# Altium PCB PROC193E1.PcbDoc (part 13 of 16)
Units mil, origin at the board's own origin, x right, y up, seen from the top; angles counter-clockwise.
Board outline 7700 x 2300 mil, 6 copper layers (Top Layer, GND 1, SIG 1, PWR, GND 2, Bottom Layer), stack 60.98 mil thick; 946 components, 667 nets, 9401 pads, 1730 vias.
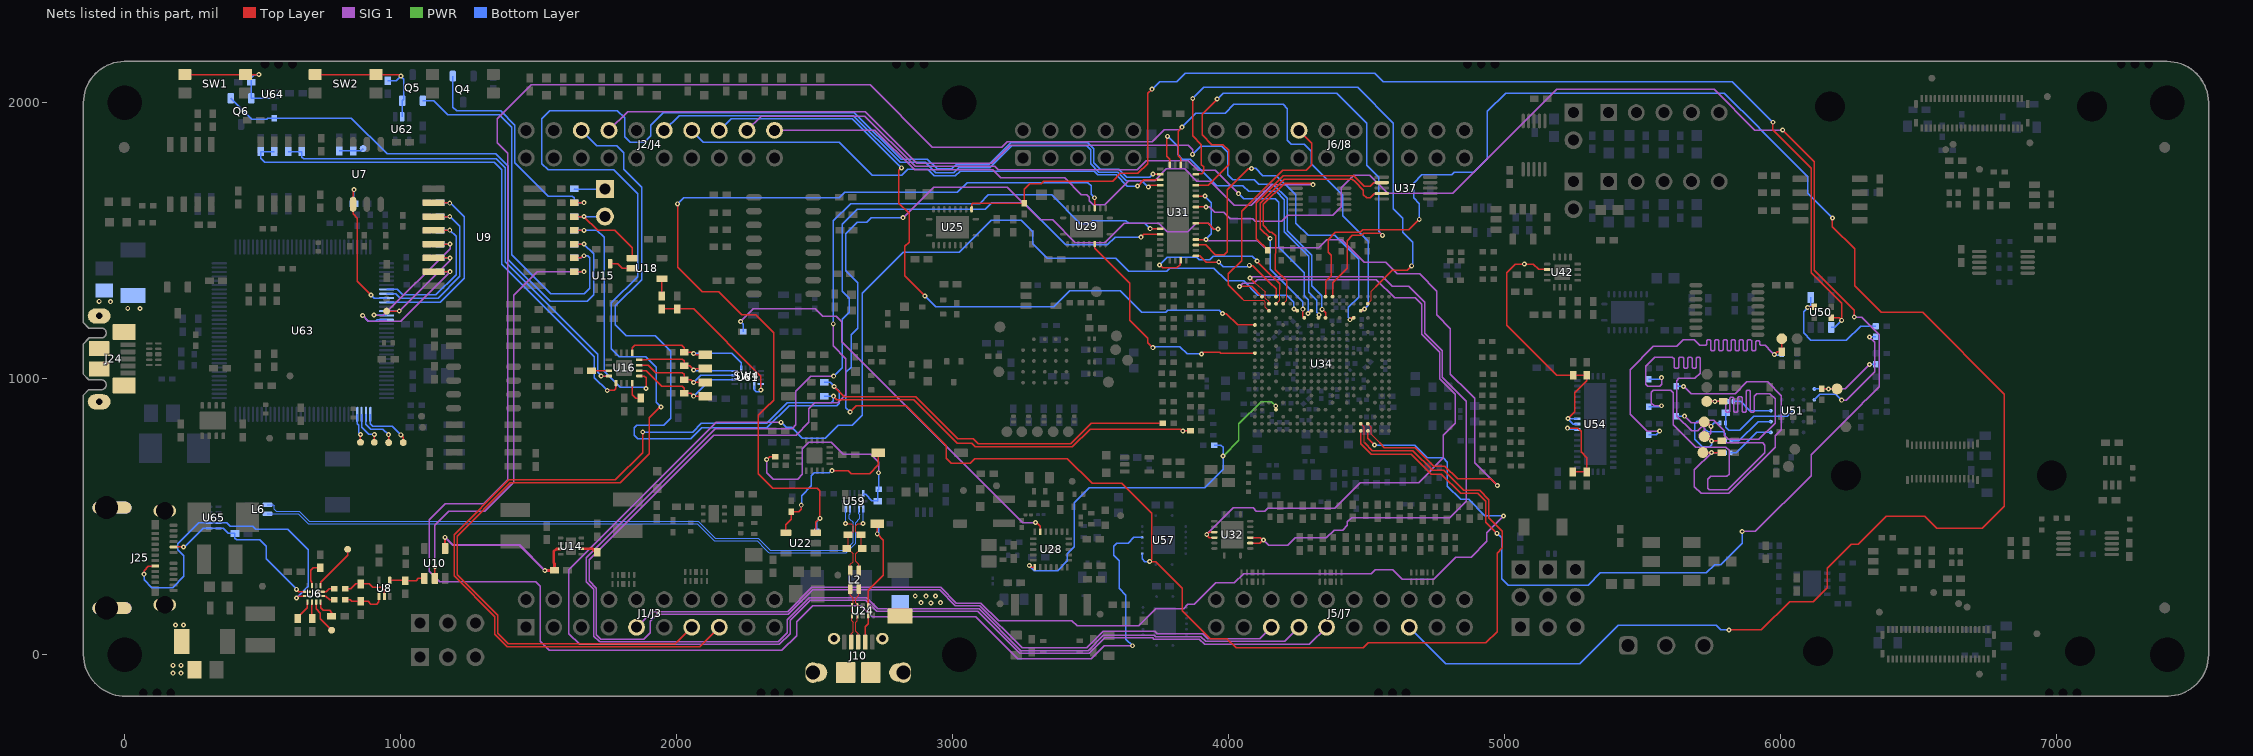
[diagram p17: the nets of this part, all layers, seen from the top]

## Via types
v1: diameter 18, hole 8, Top Layer to Bottom Layer, tented both sides, 1710 vias
v2: diameter 18, hole 8, Top Layer to Bottom Layer, tented top, 12 vias
v3: diameter 23.62, hole 11.81, Top Layer to Bottom Layer, tented both sides, 8 vias

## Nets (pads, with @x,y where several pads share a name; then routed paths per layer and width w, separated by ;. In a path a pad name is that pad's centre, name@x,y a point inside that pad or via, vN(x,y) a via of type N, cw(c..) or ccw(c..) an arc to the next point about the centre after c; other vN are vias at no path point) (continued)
OSPI1_D4_R: R204.2 R256.1 R292.2 TP39.1 | length 1490.1
  Top Layer w5.3: v1(5976.47,1087.55) 5986.85,1097.93 R204.2@6003.63,1097.93 TP39.1@6003.63,1145.32
  SIG 1 w4.75: v1(5561.09,810.56) 5515.88,810.56 5454.41,872.04 5454.41,1033.41 5538.71,1117.71 5622.8,1117.71 5647.22,1142.13 5686.03,1142.13 5707.16,1121 5725.58,1121 5727.95,1121 5731.64,1124.69 5731.64,1137.31 5735.33,1141 5742.7,1141 5746.39,1137.31 5746.39,1104.69 5750.08,1101 5757.45,1101 5761.14,1104.69 5761.14,1137.31 5764.83,1141 5772.2,1141 5775.89,1137.31 5775.89,1104.69 5779.58,1101 5786.95,1101 5790.64,1104.69 5790.64,1137.31 5794.33,1141 5801.7,1141 5805.39,1137.31 5805.39,1104.69 5809.08,1101 5816.45,1101 5820.14,1104.69 5820.14,1137.31 5823.83,1141 5831.2,1141 5834.89,1137.31 5834.89,1104.69 5838.58,1101 5845.95,1101 5849.64,1104.69 5849.64,1137.31 5853.33,1141 5860.7,1141 5864.39,1137.31 5864.39,1104.69 5868.08,1101 5875.45,1101 5879.14,1104.69 5879.14,1137.31 5882.83,1141 5890.2,1141 5893.89,1137.31 5893.89,1104.69 5897.58,1101 5904.95,1101 5908.64,1104.69 5908.64,1134.74 5912.33,1138.43 5919.7,1138.43 5923.39,1134.74 5923.39,1124.69 5927.08,1121 5943.03,1121 5965.24,1098.79 v1(5976.47,1087.55)
  Bottom Layer w5.3: R292.2@5521.14,798.02 5548.55,798.02 v1(5561.09,810.56) ; v1(5976.47,1087.55) 5978.51,1085.52 6002.46,1085.52 R256.1@6003.63,1084.35
OSPI1_D5: R268.2 U51.E3 | length 150.5
  Bottom Layer w5.3: R268.2@5827.65,917.95 5854.05,917.95 5887.66,884.34 U51.E3@5964.26,884.34
OSPI1_D5_R: R198.2 R268.1 R284.2 TP36.1 | length 1307.3
  Top Layer w5.3: TP36.1@5731.56,917.99 v1(5760.91,917.95) v1(5760.91,917.95) R198.2@5791.82,917.95
  SIG 1 w4.75: v1(5651.46,864.43) 5674.73,841.16 5699.25,841.16 5708.09,850 5756.74,850 5795.77,810.98 5795.77,795.37 5810.13,781 5920.33,781 5979,839.67 5979,926.86 5959.86,946 5913.09,946 5903.81,936.72 5903.81,881.64 5900.12,877.95 5892.75,877.95 5889.06,881.64 5889.06,954.26 5885.37,957.95 5878,957.95 5874.31,954.26 5874.31,881.64 5870.62,877.95 5863.25,877.95 5859.56,881.64 5859.56,931.49 5855.87,935.18 5848.5,935.18 5844.81,931.49 5844.81,881.64 5841.12,877.95 5833.75,877.95 5830.06,881.64 5830.06,928.95 5826.37,932.64 5819,932.64 5815.31,928.95 5815.31,881.64 5811.62,877.95 5804.25,877.95 5800.56,881.64 5800.56,914.26 5796.87,917.95 v1(5760.91,917.95)
  Bottom Layer w5.3: R284.2@5621.27,864.54 5651.35,864.54 v1(5651.46,864.43) ; v1(5760.91,917.95) R268.1@5807.57,917.95
OSPI1_D6: R272.2 U51.E2 | length 174
  Bottom Layer w5.3: R272.2@5819.22,775.07 5848.55,775.07 5918.45,844.97 U51.E2@5964.26,844.97
OSPI1_D6_R: R194.2 R272.1 R295.2 TP35.1 | length 1658.1
  Top Layer w5.3: TP35.1@5723.41,790.88 5733.29,790.88 v1(5749.1,775.07) R194.2@5785.55,775.07
  SIG 1 w4.75: v1(5568.23,902.32) 5540.61,902.32 5530.7,912.23 5530.7,952.06 5537.54,958.9 5601.25,958.9 5610.02,950.13 5610.02,832.88 5691.33,751.58 5801.03,751.58 5812.38,740.23 5812.38,654.61 5804.78,647 5745.52,647 5735.03,636.51 5735.03,604.02 5740.64,598.41 5808.32,598.41 5942.31,732.4 5942.31,759.45 5934.1,767.65 5788.42,767.65 5781,775.07 v1(5749.1,775.07)
  Bottom Layer w5.3: R295.2@5520.97,898.04 5521.18,898.25 5565.96,898.25 5568.23,900.52 v1(5568.23,902.32) ; v1(5749.1,775.07) 5749.1,760.2 5742.7,753.79 5714.8,753.79 5688.28,780.31 5688.28,836.39 5697.82,845.93 5715.61,845.93 5723.29,838.24 5723.29,819.7 5735.52,807.47 5792.53,807.47 5799,801 5799,777.69 5796.38,775.07 R272.1@5799.14,775.07
OSPI1_D7: R271.2 U51.E1 | length 175.6
  Bottom Layer w5.3: R271.2@5819.22,731.78 5839.07,731.78 5912.89,805.6 U51.E1@5964.26,805.6
OSPI1_D7_R: R193.2 R271.1 R285.2 TP33.1 | length 1266.5
  Top Layer w5.3: TP33.1@5717.64,732.72 v1(5749.1,732.7) 5750.02,731.78 R193.2@5785.55,731.78
  SIG 1 w4.75: v1(5647.75,972.46) 5674.85,945.37 5834.14,945.37 5877.35,988.58 5952.66,988.58 6002.19,939.05 6002.19,816.27 5979.46,793.54 5979.46,752.61 5811.85,585 5711,585 5687,609 5687,670.6 v1(5749.1,732.7)
  Bottom Layer w5.3: R285.2@5621.27,972.25 5647.54,972.25 v1(5647.75,972.46) ; v1(5749.1,732.7) 5749.56,732.24 5798.68,732.24 R271.1@5799.14,731.78
OSPI1_DQS: R195.2 R199.1 R273.2 U51.C3 | length 330.3
  Bottom Layer w5.3: R195.2@5800.04,877.17 5800,877.12 R273.2@5800,840 5800,824 5811,813 5851,813 5902.48,864.48 6023.13,864.48 U51.C3@6043,884.34
OSPI1_DQS_R: R273.1 R293.2 TP34.1 | length 1228.2
  Top Layer w5.3: TP34.1@5722.55,844.01 5730.67,844.01 v1(5746.91,827.76)
  SIG 1 w4.75: v1(5568.23,1003.98) 5568.23,979.41 5561.82,973 5518.01,973 5510.69,980.32 5510.69,1045.86 5543.43,1078.6 5607.4,1078.6 5613.3,1072.7 5613.3,1042.65 5617.85,1038.1 5625.75,1038.1 5630.19,1042.54 5630.19,1074.79 5634,1078.6 5645.09,1078.6 5648.77,1074.91 5648.77,1042.28 5652.46,1038.6 5659.84,1038.6 5663.52,1042.28 5663.52,1074.91 5667.21,1078.6 5674.59,1078.6 5678.27,1074.91 5678.27,1042.28 5681.96,1038.6 5689.34,1038.6 5693.02,1042.28 5693.02,1074.91 5696.71,1078.6 5704.09,1078.6 5707.77,1074.91 5707.77,1019.81 5689.09,1001.13 5630.54,1001.13 5623.09,993.68 5623.09,864.76 5676.82,811.04 5698.45,811.04 5713.31,825.9 5718.53,825.9 5723.74,820.68 5723.74,815.47 5704.67,796.4 5704.67,787.46 5712.17,779.96 5724.25,779.96 5735.17,790.88 5746.72,802.42 5746.72,827.56 v1(5746.91,827.76)
  Bottom Layer w4.75: v1(5746.91,827.76) 5759.16,840 R273.1@5779.92,840
  Bottom Layer w5.3: R293.2@5521.14,999.2 5560.02,999.2 5564.79,1003.98 v1(5568.23,1003.98)
OSPI1_ECC_FAIL: R207.1 R249.2 TP43.1 U51.A5 | length 314.6
  Top Layer w5.3: R207.1@6148.3,963.43 v1(6172.35,963.43) TP43.1@6203.88,963.43
  SIG 1 w4.75: v1(6172.35,963.43) 6233.36,963.43 v1(6321.24,1051.32)
  Bottom Layer w5.3: U51.A5@6121.74,963.08 6172,963.08 v1(6172.35,963.43) ; v1(6321.24,1051.32) 6322.31,1052.39 R249.2@6343.71,1052.39
OSPI1_MUX_EN: R186.2 R189.1 U54.8 | length 297.3
  Top Layer w5.3: v1(5227.45,820.93) 5264.55,820.93 5276.18,809.3 5276.18,734.85 5297.29,713.74 R189.1@5297.29,662.45 R186.2@5246.75,662.45
  Bottom Layer w5.3: v1(5227.45,820.93) 5232.03,816.35 U54.8@5263.12,816.35
OSPI1_MUX_SEL: R187.2 R190.1 U42.10 U54.9 U54.10 | length 987
  Top Layer w5.3: U42.10@5153.4,1396.06 5123.08,1396.06 5103.39,1415.74 v1(5070.7,1415.74) 5038.35,1415.74 5007.2,1384.59 5007.2,1194.57 5088.74,1113.03 5188.8,1012.97 R187.2@5247.81,1012.97 ; v1(5228.77,855.72) 5254.15,881.1 5254.15,949.53 5297.67,993.06 R190.1@5297.67,1012.97 R187.2@5247.81,1012.97 ; R187.2@5248.75,1012.03 R187.2@5247.81,1012.97
  Bottom Layer w5.3: U54.9@5263.12,836.03 5248.45,836.03 v1(5228.77,855.72) U54.10@5263.12,855.72
OSPI1_RESET_OUT0: R93.2 R208.1 U25.12 U50.1 | length 4280.2
  Top Layer w5.3: U25.12@3067.87,1614.03 3067.87,1631.81 3072.56,1636.5 R93.2@3258.14,1636.5 3258.14,1686.14 3278.82,1706.82 3320.61,1706.82 3329.98,1716.2 3578.69,1716.2 3607.11,1744.61 3670.42,1744.61 3705.83,1780.03 3705.83,2034.45 v1(3722.17,2049.21) ; v1(5971.5,1929.49) 5971.5,1902.37 6110.42,1763.45 6110.42,1383.57 6220.63,1273.37 v1(6220.63,1211.87) 6211.55,1220.95 R208.1@6182.93,1220.95
  Bottom Layer w5.3: v1(3722.17,2049.21) 3722.39,2049.21 3749.54,2076.36 3812.03,2076.36 3843.02,2107.35 4529.36,2107.35 4560.35,2076.36 5824.63,2076.36 v1(5971.5,1929.49) ; U50.1@6182.93,1186.5 6195.25,1186.5 v1(6220.63,1211.87)
OSPI1_RSTn: R247.2 U51.A4 | length 435.8
  SIG 1 w4.75: v1(6220.63,922.47) 6237.35,922.47 6340.77,1025.89 6340.77,1131.82 v1(6321.24,1151.35)
  Bottom Layer w5.3: U51.A4@6121.74,923.71 6141.55,943.52 6199.57,943.52 v1(6220.63,922.47) ; v1(6321.24,1151.35) 6321.7,1151.81 R247.2@6344.52,1151.81
OSPI1_RSTn_R: R206.1 R241.1 R247.1 U50.4 | length 459.3
  Top Layer w5.3: v1(6097.5,1257.86) 6100.94,1257.86 6103.4,1260.32 R206.1@6121.79,1260.32
  Bottom Layer w5.3: U50.4@6108.12,1294.77 6108.12,1266.82 6099.16,1257.86 v1(6097.5,1257.86) 6082.58,1242.93 6082.58,1166.39 6108.97,1139.99 6237.78,1139.99 6288.97,1191.18 R247.1@6344.52,1191.18
PMIC_INTn_GPIO0: R322.1 U28.13 U34.U4 | length 1435.5
  Top Layer w5.3: v1(3277.12,323.02) 3278.06,323.02 3284.01,317.07 U28.13@3296.9,317.07 ; v1(4170.16,901.47) 4170.16,889.25 U34.U4@4171.26,888.16
  PWR w4.75: v1(3979.2,719.87) 4036.41,777.09 4036.41,836.41 4117,917 4154.63,917 v1(4170.16,901.47)
  Bottom Layer w5.3: v1(3277.12,323.02) 3295.38,304.77 3379.73,304.77 3414.94,339.98 3414.94,366.24 3439.69,390.99 3439.69,550.57 3494.32,605.2 3912.65,605.2 3979.2,671.75 v1(3979.2,719.87) 3979.2,751.51 3971.18,759.53 R322.1@3947.06,759.53
PMIC_NRST: R365.1 U28.6 | length 1533.2
  Top Layer w5.3: v1(3300,478.86) 3302.43,476.43 3306.01,476.43 3316.58,465.85 U28.6@3316.58,446.5
  SIG 1 w4.75: v1(2231.35,1207.91) 2277.09,1253.66 2501.76,1253.66 2528.33,1227.09 2576.86,1227.09 2597.54,1206.4 2597.54,1134.49 3253.17,478.86 v1(3300,478.86)
  Bottom Layer w5.3: v1(2231.35,1207.91) 2240.87,1198.39 R365.1@2240.87,1170.68
PORZ_DELAY: U15.4 U18.2 | length 86.3
  Top Layer w5.3: U15.4@1758.55,1416.81 1785.92,1416.81 1802.85,1399.88 U18.2@1837.83,1399.88
PORZ_PB: Q6.2 R410.1 SW1.2 SW1.4 U64.1 | length 436
  Top Layer w5.3: SW1.2@217.32,2102.28 SW1.4@437.8,2102.28 v1(485.53,2102.28)
  Bottom Layer w5.3: Q6.2@458.54,2016.24 458.02,2016.77 R410.1@458.02,2074.5 458.02,2090.5 469.81,2102.28 v1(485.53,2102.28) ; Q6.2@458.71,2016.42 U64.1@519.68,2016.42
PR1_PRU0_GPIO0: J2/J4.11 U34.B5 | length 2828.6
  Top Layer w3.94: U34.B5@4196.85,1272.01 4209.64,1284.81 4209.64,1325.16
  Top Layer w5.3: 4209.64,1325.16 4209.64,1354.54 4168.79,1395.4 4168.79,1399.79 4169.58,1508.29 4169.58,1518.19 4156.04,1531.73 4148.61,1531.73 4124.7,1555.63 4124.7,1631.9 4202.17,1709.37 4295.19,1709.37 4301.14,1703.43 v1(4304.58,1703.43)
  SIG 1 w4.75: J2/J4.11@2354.17,1900 2718,1900 2861.45,1756.55 3144.45,1756.55 3173.4,1727.6 3405.08,1727.6 3465.78,1666.9 3466.43,1666.9 3466.53,1666.8 3481.75,1666.8 3481.85,1666.9 3486.18,1666.9 3494.62,1658.46 3494.62,1645.33 3509.55,1630.4 3550.13,1630.4 3637.55,1717.82 3730.82,1717.82 3773.38,1760.38 3839.62,1760.38 3884.11,1715.89 3932.07,1715.89 4019.17,1628.8 4081.34,1628.8 4155.96,1703.43 v1(4304.58,1703.43)
PR1_PRU0_GPIO1: U31.22 U34.A4 | length 371.7
  Top Layer w5.3: U31.22@3881.04,1445.5 3895.43,1445.5 3917.88,1423.04 v1(3963.61,1423.04) ; v1(4074.24,1411.06) 4074.92,1410.38 4086.93,1410.38 4148.88,1348.43 4171.26,1326.05 4171.26,1313.55 U34.A4@4171.26,1297.6
  Bottom Layer w5.3: v1(3963.61,1423.04) 3979.88,1406.77 4066.52,1406.77 4070.8,1411.06 v1(4074.24,1411.06)
PR1_PRU0_GPIO2: U31.20 U34.B4 | length 677
  Top Layer w3.94: U34.B4@4171.26,1272.01 4184.05,1284.81 4184.05,1325.16
  Top Layer w5.3: v1(3749.2,1412.38) 3749.53,1412.38 3760.42,1401.5 3812.21,1401.5 3823.65,1412.94 3823.65,1427.48 U31.20@3825.92,1429.75 ; v1(4103,1427) 4103,1424.85 4128.3,1399.55 4184.05,1343.8 4184.05,1325.16
  Bottom Layer w5.3: v1(3749.2,1412.38) 3777.66,1440.84 3883.95,1440.84 3892.68,1432.11 3931.63,1432.11 3944.13,1444.61 4085.39,1444.61 v1(4103,1427)
PR1_PRU0_GPIO5: U32.11 U32.12 U34.B3 | length 2500
  Top Layer w3.94: 4094.91,1348.43 4131.52,1315.1 4132.81,1313.82 4132.81,1302.97 4132.87,1302.9 4132.87,1291.45 4143.88,1280.45 4143.88,1273.8 U34.B3@4145.67,1272.01
  Top Layer w5.3: v1(4076.31,1365.36) 4094.91,1348.43 ; U32.11@4077.76,404.97 4112.62,404.97 v1@4122.8,415.14 ; U32.12@4077.76,424.65 4113.2,424.65 4122.71,415.14 v1@4122.8,415.14 ; v1@4126.14,415.14 v1@4122.8,415.14 ; v1(4126.14,415.42) 4123.07,415.42 v1@4122.8,415.14
  SIG 1 w4.75: v1(4076.31,1365.36) 4079.9,1365.36 4083.89,1369.35 4557.02,1369.35 4591.5,1334.87 4652.08,1334.87 4710.4,1276.54 4710.4,1164.29 4773.67,1101.01 4773.67,1005.15 4860.2,918.62 4860.2,556.87 4800.4,497.08 4445.28,497.08 4429.79,481.58 4429.79,468.61 4412.56,451.39 4381.38,451.39 4353.9,423.91 4240.34,423.91 4213.49,397.06 4144.5,397.06 v1(4126.14,415.42)
PR1_PRU0_GPIO6: U32.4 U32.5 U34.A2 | length 2474.4
  Top Layer w5.3: U32.5@3947.84,424.65 3929.76,424.65 3920.05,434.36 v1(3920.05,436.01) 3920.7,436.01 3929.03,444.34 U32.4@3947.84,444.34 ; v1(4039.25,1334.87) 4082.81,1334.87 U34.A2@4120.08,1297.6
  SIG 1 w4.75: v1(4039.25,1334.87) 4050.22,1345.83 4089.15,1345.83 4102.92,1359.6 4534.99,1359.6 4601.25,1293.34 4676.41,1293.34 4698.88,1270.87 4698.88,1160.82 4763.92,1095.77 4763.92,1000.05 4820,943.97 4820,839.2 4777.12,796.33 4777.12,713.12 4687.35,623.35 4649.81,623.35 4649.81,623.15
  SIG 1 w5.3: v1(3920.05,436.01) 4016.05,532 4088.46,532 4099.55,520.91 4131.1,520.91 4141.97,531.78 4384.1,531.78 4475.47,623.15 4649.81,623.15
PR1_PRU0_GPIO7: U34.D8 U37.4 | length 1002.7
  Top Layer w5.3: v1(4150.06,1508.43) 4114.1,1544.39 4114.1,1636.29 4201.54,1723.73 4447.3,1723.73 4457.41,1713.62 4487.89,1683.15 4487.89,1666.56 4499.26,1655.19 4512.89,1655.19 4527.86,1670.15 4553.02,1670.15 U37.4@4554.27,1671.4 ; v1(4268.07,1252.23) 4268.07,1226.38 U34.D8@4273.62,1220.83
  Bottom Layer w5.3: v1(4150.06,1508.43) 4150.06,1397.46 4199.09,1348.43 4268.07,1279.45 v1(4268.07,1252.23)
PR1_PRU0_GPIO8: J6/J8.57 U34.C3 | length 951
  Top Layer w3.94: 4048.24,1290.58 4054.02,1284.81 4125.98,1284.81 4132.96,1277.83 4132.96,1277.4 4132.87,1277.31 4132.87,1259.22 U34.C3@4145.67,1246.42
  Top Layer w5.3: 4048.24,1290.58 3998.46,1340.37 3998.46,1380.46 4046.6,1428.6 4046.6,1536.54 4046.43,1536.71 4046.43,1552.89 4046.6,1553.06 4046.6,1607.32 4194.73,1755.45 4280.06,1755.45 4300.22,1775.61 4300.22,1853.95 J6/J8.57@4254.17,1900
PR1_PRU0_GPIO9: R133.1 U37.2 | length 705
  Top Layer w5.3: R133.1@4140.45,1465.23 4140.45,1467.2 4099.9,1507.75 4099.9,1626.92 4099.9,1637.08 4198.1,1735.28 4452.85,1735.28 4490.84,1697.29 4512.66,1697.29 4525.37,1710 4553.51,1710 U37.2@4554.27,1710.77
PR1_PRU1_GPIO0: U31.28 U34.W16 U57.10 | length 6452.4
  Top Layer w3.94: U34.W16@4478.34,836.97 4491.14,824.18 4491.14,768.57 4491.87,767.84
  Top Layer w5.3: v1(2628.07,880.01) 2650.1,902.04 2832.07,902.04 2976.16,757.95 2976.16,711.67 2993.97,693.86 3062.73,693.86 3080,711.13 3415.21,711.13 3504.49,621.85 3611.35,621.85 3611.64,621.57 3612.06,621.57 3721.06,512.57 3721.06,345.63 v1(3713.33,337.9) 3735.19,337.9 3831.36,241.73 3831.36,160.43 3932.82,58.96 3992.14,58.96 4026.38,24.72 4035.88,24.72 4222.29,24.72 4482.79,24.72 4486.91,24.72 4505.65,43.46 4931.16,43.46 4972,84.3 4972,368.25 4990.81,387.07 4990.81,448.36 4942.13,497.03 4942.13,561.96 4908.44,595.65 4907.04,595.65 4906.89,595.8 4850.79,595.8 4778.71,667.88 4738.8,667.88 4666.72,739.95 4519.76,739.95 4491.87,767.84 ; U31.28@3881.04,1563.61 3900.05,1563.61 3900.18,1563.73 3908.57,1563.73 3908.78,1563.95 3908.97,1563.77 3925.15,1563.77 3946.32,1542.59 v1(3960.53,1542.59)
  SIG 1 w4.75: v1(2819.73,1583.71) 2930.38,1694.36 3197.62,1694.36 3316.38,1575.6 3362.12,1575.6 3444.3,1493.42 3546.46,1493.42 3546.76,1493.72 3550.94,1493.72 3621.17,1563.95 3746.99,1563.95 3777.6,1533.34 3778.11,1532.83 3851.31,1532.83 3882.25,1563.77 3924.96,1563.77 3946.13,1542.59 v1(3960.53,1542.59)
  Bottom Layer w5.3: v1(2628.07,880.01) 2612.28,895.8 2612.28,1023.29 2631.5,1042.52 2631.5,1159.02 2655.9,1183.41 2655.9,1347.2 2611.47,1391.62 2611.47,1526.06 2653.13,1567.72 2688.57,1567.72 2704.57,1583.71 v1(2819.73,1583.71) ; U57.10@3686.31,366.41 3686.31,347.3 3696,337.61 v1@3713.04,337.61
PR1_PRU1_GPIO1: U31.31 U34.Y16 | length 6227.5
  Top Layer w5.3: U31.31@3881.04,1622.66 v1(3917.06,1622.66) ; U34.Y16@4478.34,811.38 4478.34,765.07 4516.84,726.57 4660.54,726.57 4732.88,654.24 4770.64,654.24 4839.67,585.2 4902.5,585.2 4931.53,556.17 4931.53,484.46 ; 4931.51,484.43 4931.51,480.04 v1(4971.28,440.27) ; v1(6006.75,1901.33) 6121.02,1787.06 6121.02,1393.9 6266.12,1248.81 v1(6266.12,1223.61)
  SIG 1 w4.75: v1(3917.06,1622.66) 3929.39,1622.66 3949.48,1602.57 3982.5,1602.57 4004.65,1580.42 4086.16,1580.42 4096.57,1570.01 4191.76,1570.01 4213.72,1591.97 4376.94,1591.97 4407.52,1622.55 4407.52,1691.39 4453,1736.87 4510.73,1736.87 4575.85,1671.75 4811.01,1671.75 5187.84,2048.57 5758.43,2048.57 5905.67,1901.33 v1(6006.75,1901.33) ; v1(5860.13,447.11) 5908.28,447.11 6110.17,649 6110.17,724.35 6295.62,909.81 6295.62,910.61 6306.39,921.38 6307.19,921.38 6356.33,970.52 6356.33,1160.5 6293.22,1223.61 v1(6266.12,1223.61)
  Bottom Layer w5.3: v1(4971.28,440.27) 4988.11,423.45 4988.11,276.36 5012.39,252.08 5038.58,252.08 5038.76,252.26 5074.39,252.26 5074.57,252.08 5138.58,252.08 5138.76,252.26 5174.39,252.26 5174.57,252.08 5238.58,252.08 5238.76,252.26 5274.39,252.26 5274.57,252.08 5301.85,252.08 5346.36,296.58 5730.4,296.58 5760.2,326.38 5781.76,326.38 5860.13,404.75 v1(5860.13,447.11)
PR1_PRU1_GPIO2: U31.25 U31.33 U34.W17 | length 2555.4
  Top Layer w3.94: U34.W17@4503.93,836.97 4516.73,824.18 4516.73,816.68 4516.73,806.08 ; 4516.72,806.07 4516.72,798.65 4519.87,795.5 4547.51,767.84 4546.59,767.84
  Top Layer w5.3: U31.25@3881.04,1504.55 3881.18,1504.69 3916.92,1504.69 v1(3917.06,1504.83) ; U31.33@3881.04,1662.03 v1(3913.33,1662.03) ; 4546.59,767.84 4563.58,750.85 4564.52,750.85 4564.82,750.55 4674.79,750.55 4742.32,683.03 4782.84,683.03 4828.83,637.04 4949.14,637.04 v1(4972.77,613.42)
  SIG 1 w4.75: v1(3917.06,1504.83) 3921.4,1500.48 4104.98,1500.48 4130.49,1474.98 4325.26,1474.98 4354.39,1504.11 4409.86,1504.11 4491.64,1422.33 4567.79,1422.33 4610.35,1379.76 4691.21,1379.76 4753.92,1317.05 4753.92,1230.35 4754.61,1229.66 4754.61,1229.5 4802.92,1181.2 4802.92,1126.67 4802.77,1126.52 4802.77,1106.64 4802.92,1106.48 4802.92,1021 4802.92,1017.29 4869.22,950.99 4891,929.21 4891,695.18 v1(4972.77,613.42)
  Bottom Layer w5.3: v1(3913.33,1662.03) 3937.3,1638.06 3937.3,1525.06 v1(3917.06,1504.83)
PR1_PRU1_GPIO3: U31.35 U34.A12 | length 1865.5
  Top Layer w5.3: U31.35@3881.04,1701.4 3925.12,1701.4 3999.65,1775.94 3999.65,1827.51 3978.52,1848.65 3938.84,1848.65 3903.64,1883.85 3903.64,1959.35 v1(3957.85,2013.56) ; U34.A12@4375.98,1297.6 4375.98,1347.07 4377.34,1348.43 4428.76,1399.85 4428.76,1500.95 4447.36,1519.54 4482.04,1519.54 4489.67,1527.17 4549.29,1527.17 v1(4556.67,1519.78)
  Bottom Layer w5.3: v1(3957.85,2013.56) 3979.54,2035.25 4390.41,2035.25 4499.89,1925.77 4499.89,1781.68 4499.89,1773.37 4542.59,1730.66 4542.59,1600.52 4542.59,1533.86 v1(4556.67,1519.78)
PR1_PRU1_GPIO4: J2/J4.17 U34.D11 | length 3242.4
  Top Layer w5.3: v1(4338.31,1251.74) 4350.39,1239.65 U34.D11@4350.39,1220.83
  SIG 1 w4.75: J2/J4.17@1754.17,1900 1822.39,1968.22 2682.42,1968.22 2870.09,1780.55 3141.83,1780.55 3207.56,1846.28 3852.76,1846.28 3868.6,1830.44 v1(3868.6,1813.52)
  Bottom Layer w5.3: v1(3868.6,1813.52) 3897.95,1842.87 3975.2,1842.87 3996.74,1821.33 3996.74,1739.64 4015.08,1721.3 4091.43,1721.3 4108.01,1704.72 4159.83,1704.72 4211.25,1653.3 4211.25,1536.67 4300.17,1447.75 4300.17,1337.9 4337.6,1300.48 4337.6,1252.45 v1(4338.31,1251.74)
PR1_PRU1_GPIO5: J2/J4.13 U34.E1 | length 2564.7
  Top Layer w5.3: v1(2813.98,1764.39) 2804.39,1754.8 2804.39,1636.55 2841.73,1599.21 2841.73,1495.32 2826.32,1479.91 2826.32,1372.66 v1(2898.74,1300.24) ; v1(3976.69,1236.43) 3991.46,1236.43 4032.65,1195.24 U34.E1@4094.49,1195.24
  Bottom Layer w5.3: J2/J4.13@2154.17,1900 2196.81,1942.64 2635.67,1942.64 v1@2813.92,1764.39 ; v1(2898.74,1300.24) 2937.47,1261.51 3366.06,1261.51 3423.66,1319.1 3606.02,1319.1 3684.64,1240.48 3771.01,1240.48 3778.89,1248.37 3964.76,1248.37 v1(3976.69,1236.43)
PR1_PRU1_GPIO6: J5/J7.48 U34.A11 | length 6626.1
  Top Layer w5.3: U34.A11@4350.39,1297.6 4350.39,1353.06 4371.29,1373.96 4371.29,1448.27 4360.29,1459.26 4360.29,1504.44 4385.99,1530.14 4475.46,1530.14 4485.28,1539.96 4652.84,1539.96 4690.09,1577.21 v1(4690.09,1577.76) ; v1(5812.07,89.95) 5929.28,89.95 6031.54,192.21 6118.08,192.21 6168.85,242.98 6168.85,313.19 6255.99,400.34 6280.9,400.34 6382.11,501.54 6522.05,501.54 6565.88,457.71 6730.04,457.71 6809.81,537.48 6809.81,944.46 6513.67,1240.6 6363.07,1240.6 6267.13,1336.54 6267.13,1470.71 6187,1550.84 v1(6187,1583)
  Bottom Layer w5.3: J5/J7.48@4654.17,100 4786.92,-32.75 5271.74,-32.75 5410.98,106.49 5765.5,106.49 5782.03,89.95 v1(5812.07,89.95) ; v1(4690.09,1577.76) 4690.09,1634.24 4669.25,1655.08 4669.25,1708.98 4699.59,1739.32 4807.87,1739.32 4816.68,1748.13 4887.96,1748.13 4937.17,1797.34 4937.17,1969.35 5002.98,2035.16 5794.65,2035.16 5921.08,1908.72 5921.08,1908.6 5950.62,1879.06 5950.74,1879.06 6097.71,1732.1 6097.71,1672.29 v1(6187,1583)
PR1_PRU1_GPIO7: U31.24 U34.D15 | length 1314.1
  Top Layer w5.3: U31.24@3881.04,1484.87 3916.21,1484.87 3951.57,1449.51 3983.52,1449.51 3994.33,1460.32 3994.33,1684.88 4070.33,1760.88 4081.38,1760.88 v1(4082.54,1762.04) ; v1(4438.87,1213.91) 4441.3,1216.34 4445.79,1220.83 U34.D15@4452.75,1220.83
  Bottom Layer w5.3: v1(4082.54,1762.04) 4097.03,1762.04 4122.54,1736.53 4172.4,1736.53 4242.57,1666.36 4242.57,1564.45 4287.03,1519.99 4383.25,1519.99 4470.33,1432.9 4470.33,1295.38 4433.66,1258.71 4433.66,1222.56 4438.87,1217.35 v1(4438.87,1213.91)
PR1_PRU1_GPIO9: J1/J3.5 U34.Y17 | length 4159.6
  Top Layer w5.3: U34.Y17@4503.93,811.38 4503.93,783.9 v1(4528.15,759.68)
  SIG 1 w4.75: J1/J3.5@1854.17,100 1910.95,156.78 2401.25,156.78 2489.44,244.96 2955.98,244.96 3013.29,187.65 3102.15,187.65 3165.76,124.04 3431.53,124.04 3450.94,104.62 3673.91,104.62 3735.73,166.44 3836.02,166.44 3851.87,182.3 3874.24,182.3 3953.59,261.64 4020.64,261.64 4053.34,294.34 4516.11,294.34 4529.98,308.21 4593.7,308.21 4628.68,273.23 4742.23,273.23 4823,354 4878.64,354 4935.17,410.53 4935.17,442.72 v1(4995.64,503.19)
  Bottom Layer w5.3: v1(4528.15,759.68) 4673.75,759.68 4719.88,713.55 4776.78,713.55 4792.02,698.31 4792.02,610.37 4839.56,562.83 4868.5,562.83 4928.14,503.19 v1(4995.64,503.19)
PR1_PRU1_GPIO10: U31.40 U34.C16 U57.13 | length 9456.6
  Top Layer w5.3: U31.40@3825.92,1776.2 3825.92,1798.89 3816.25,1808.57 3816.25,1896.8 3830.2,1910.75 v1(3830.2,1911.63) ; U34.C16@4478.34,1246.42 4480.64,1246.42 4485.05,1246.42 v1(4491.93,1253.31)
  SIG 1 w4.75: 3458.26,-14.13 3234.98,-14.13 3082.86,138 2708.72,138 2668.45,178.27 2492.98,178.27 2433.72,119.01 2433.72,69.7 2381.15,17.13 1537.38,17.13 1506.14,48.36 1506.14,247.78 1489.23,264.69 1141.22,264.69 1102.71,303.19 1102.71,489.14 1161.42,547.84 1301.15,547.84 1387.06,633.75 1387.06,1817.94 1349.5,1855.5 1349.5,1941.43 1472.57,2064.5 2700.5,2064.5 2926,1839 3178,1839 3197.46,1858.46 3722.46,1858.46 3766.77,1902.77 3820.79,1902.77 3829.65,1911.63 v1(3830.2,1911.63) ; 3458.27,-14.12 3502.04,-14.12 3548.98,32.82 v1(3651.24,32.82)
  Bottom Layer w5.3: v1(3651.24,32.82) 3651.1,32.82 3627.03,56.89 3627.03,216.46 3603.03,240.45 3603.03,340.73 3582.6,361.16 3582.6,392.62 3594.78,404.8 3635.49,404.8 3656.11,425.42 3686.25,425.42 U57.13@3686.31,425.47 ; v1(3830.2,1911.63) 3880.81,1962.24 3986.77,1962.24 4018.38,1993.85 4197.4,1993.85 4211.94,1979.31 4211.94,1863.94 4225.88,1850 4272.87,1850 4298.94,1823.94 4298.94,1779.47 4412.78,1665.63 4412.78,1589.97 4504.97,1497.77 4504.97,1266.35 v1(4491.93,1253.31)
PR1_PRU1_GPIO11: J1/J3.8 R128.1 R358.1 | length 4350.3
  Top Layer w5.3: v1(1876.62,806.99) 1876.62,732.62 1777.75,633.75 1391.89,633.75 1193.05,434.91 1193.05,285.71 1340.58,138.18 1340.58,74.53 1385.26,29.86 2084.03,29.86 J1/J3.8@2154.17,100 ; v1(2567.3,936.88) 2579.86,924.32 2858.88,924.32 3016.06,767.13 3068.25,767.13 3082.22,753.16 3433.32,753.16 3497.83,817.67 3826.15,817.67 v1(3833.4,810.41) 3834.24,811.26 R128.1@3861.2,811.26
  Bottom Layer w5.3: v1(1876.62,806.99) 2057.43,806.99 2089.3,838.85 2325.94,838.85 2401.07,913.98 2559.98,913.98 2567.3,921.29 v1(2567.3,936.88) R358.1@2534.55,936.88
PR1_PRU1_GPIO12: J2/J4.18 R119.1 R359.1 | length 3749.8
  Top Layer w5.3: v1(2570.28,971.88) 2606.46,935.71 2865.41,935.71 3017.76,783.36 3074.64,783.36 3092.99,765.01 3427.02,765.01 3501.37,839.37 R119.1@3761.42,839.37
  Bottom Layer w5.3: J2/J4.18@1654.17,1900 1709.54,1844.64 1783.17,1844.64 1808.18,1819.63 1808.18,1758.7 1872.55,1694.33 1872.55,1359.01 1777.78,1264.24 1777.78,1195.82 1817.46,1156.14 1921.67,1156.14 1977.74,1100.07 1977.74,857.14 1951.91,831.31 1855.8,831.31 1846.44,821.96 1846.44,794.98 1858.39,783.03 2051.25,783.03 2090.21,821.99 2326.5,821.99 2406.75,902.24 2579.57,902.24 2587.88,910.55 2587.88,954.28 v1(2570.28,971.88) 2555.28,986.88 R359.1@2534.55,986.88
PR1_PRU1_GPIO13: U31.37 U34.B17 | length 1894.5
  Top Layer w3.94: U34.B17@4503.93,1272.01 4516.73,1284.81 4516.73,1292.3 4516.73,1317.81 4533.09,1334.17
  Top Layer w5.3: v1(3869.34,2015.99) 3869.23,2015.88 3869.23,1880.03 3901,1848.26 3901,1776.2 3909.76,1767.45 3909.76,1751.69 3901.1,1743.04 3883.31,1743.04 U31.37@3881.04,1740.77 ; 4533.09,1334.17 4547.35,1348.43 4592.44,1393.52 4646.63,1393.52 v1(4662.59,1409.48)
  Bottom Layer w5.3: v1(3869.34,2015.99) 3909.2,2055.85 4467.42,2055.85 4596.68,1926.6 4596.68,1616.04 4630.34,1582.37 4630.34,1531.25 4666.73,1494.86 4666.73,1417.06 4662.59,1412.92 v1(4662.59,1409.48)
PR1_PRU1_GPIO15: J2/J4.12 U34.C9 | length 2568.7
  Top Layer w5.3: v1(4287.24,1236.62) 4297.04,1246.42 U34.C9@4299.21,1246.42
  SIG 1 w4.75: J2/J4.12@2254.17,1900 2305.81,1951.64 2681.69,1951.64 2863.87,1769.45 3152.55,1769.45 3165.31,1756.69 3667.5,1756.69 3700.45,1789.63 3853.94,1789.63 3888.42,1755.16 3951.16,1755.16 v1(4035.56,1670.76)
  Bottom Layer w5.3: v1(4035.56,1670.76) 4053.71,1652.61 4167.55,1652.61 4180.15,1640.01 4180.15,1477.08 4273.62,1383.62 4273.62,1300.62 4288.64,1285.6 4288.64,1238.02 v1(4287.24,1236.62)
PR1_PRU1_GPIO16: U31.42 U34.D10 | length 1123.3
  Top Layer w5.3: v1(3778.35,1878.42) 3776.02,1876.1 3776.02,1805.97 3786.55,1795.44 U31.42@3786.55,1776.2 ; U34.D10@4324.8,1220.83 4326.84,1222.88 v1(4326.84,1231.96)
  Bottom Layer w5.3: v1(3778.35,1878.42) 3815.03,1841.75 3815.03,1812.84 3832.11,1795.76 3860.27,1795.76 3955.7,1700.32 4050.16,1700.32 4052,1698.48 4052.43,1698.48 4072.13,1678.78 4171.21,1678.78 4200.95,1649.04 4200.95,1531.98 4289.57,1443.36 4289.57,1313.75 4318.78,1284.54 4318.78,1241.41 4326.84,1233.36 v1(4326.84,1231.96)
PR1_PRU1_GPIO19: J5/J7.45 U34.C7 | length 6882.4
  Top Layer w4.75: v1(4236.18,1253.35) 4243.11,1246.42 U34.C7@4248.03,1246.42
  SIG 1 w4.75: v1(2377.9,842.25) 2377.42,842.73 2142.74,842.73 1609.05,309.04 1609.05,76.52 1647.81,37.76 1716.88,37.76 1717.12,37.52 2371.96,37.52 2410.27,75.83 2410.27,124.43 2483.61,197.77 2684.56,197.77 2724.83,157.5 3090.94,157.5 3243.06,5.38 3493.96,5.38 3550.04,61.45 3723.78,61.45 3728.77,56.46 3893.14,56.46 3912.18,37.43 4291.6,37.43 J5/J7.45@4354.17,100
  Bottom Layer w5.3: v1(2377.9,842.25) 2396.56,823.6 2416.31,823.6 2455.09,784.82 2537.75,784.82 2584.41,831.48 2635.76,831.48 2671.65,867.37 2671.65,1310.41 2820.61,1459.37 3023.31,1459.37 3138.54,1574.6 3247.4,1574.6 3290.09,1531.91 3290.09,1489.91 3342.82,1437.18 3589.83,1437.18 3601.51,1425.51 3601.75,1425.51 3637.7,1389.55 3774.56,1389.55 3786.44,1401.43 3945.43,1401.43 3992.51,1354.36 4053.87,1354.36 4105.75,1302.48 4210.75,1302.48 4236.18,1277.05 v1(4236.18,1253.35)
RESETN_PB: Q5.2 R395.1 SW2.2 SW2.4 U62.2 | length 521.1
  Top Layer w5.3: SW2.2@689.76,2102.28 SW2.4@910.24,2102.28 994.46,2102.28 v1(1000,2096.74)
  Bottom Layer w5.3: R395.1@952.36,2080.18 983.43,2080.18 v1(1000,2096.74) 1011.05,2085.69 1011.05,2013.29 Q5.2@1005.32,2007.56 U62.2@1005.32,1949.65
SHIELD1: C1.2 J25.1 J25.2 J25.3 J25.4 R3.1
  other v1: 175.1,-66.69 203.76,-66.69 175.1,-38.02 203.76,-38.02 183.7,107.99 212.36,107.99
SHIELD4: C271.2 J24.6 J24.7 J24.8 J24.9 J24.10 J24.11 R416.1
  other v1: 10.71,1255.26 55.5,1255.13 -51.58,1279.52 -92.91,1280.67
SHIELD5: C57.2 J10.6 J10.7 J10.8 J10.9 J10.10 J10.11 R352.1
  other v1: 2920.18,187.94 2884.33,188.76 2954.99,188.91 2903.06,212.32 2864,212.66 2937.28,213.35
SOP0_SW: R46.2 SW4.8 U16.2 U61.6 | length 462.4
  Top Layer w5.3: U16.2@1864.25,1029.69 1889.24,1029.69 1945.86,973.08 2019.74,973.08 2026.48,966.34 R46.2@2026.48,946.88 2050.18,946.88 2060.18,936.88 v1(2061.23,936.88) SW4.8@2103.23,936.88
  Bottom Layer w5.3: v1(2061.23,936.88) 2121.63,997.28 U61.6@2209.76,997.28
SOP1_SW: R47.2 SW4.7 U16.3 U61.7 | length 435.6
  Top Layer w5.3: U16.3@1864.25,1049.38 1896.32,1049.38 1923.51,1022.2 2020.62,1022.2 2026.48,1016.34 R47.2@2026.48,996.88 2050.18,996.88 2060.18,986.88 v1(2061.23,986.88) SW4.7@2103.23,986.88
  Bottom Layer w5.3: v1(2061.23,986.88) 2087.38,1013.03 U61.7@2209.76,1013.03
SOP2_SW: R48.2 SW4.6 U16.4 U61.8 | length 418.9
  Top Layer w5.3: U16.4@1864.25,1069.06 1893.68,1069.06 1896.02,1071.4 2020.13,1071.4 2026.48,1065.05 R48.2@2026.48,1046.88 2046.23,1046.88 v1(2061.23,1031.88) 2066.23,1036.88 SW4.6@2103.23,1036.88
  Bottom Layer w5.3: v1(2061.23,1031.88) 2064.34,1028.77 U61.8@2209.76,1028.77
SOP3_SW: R49.2 SW4.5 U16.5 U61.9 | length 516.9
  Top Layer w5.3: U16.5@1838.66,1094.65 1838.66,1112.72 1847.17,1121.23 2018.07,1121.23 2026.48,1112.82 R49.2@2026.48,1096.88 2052.79,1096.88 2057.79,1091.88 v1(2061.23,1091.88) 2066.23,1086.88 SW4.5@2103.23,1086.88
  Bottom Layer w5.3: v1(2061.23,1091.88) 2198.89,1091.88 2233.38,1057.39 U61.9@2233.38,1036.65
SOP_DRIVE_OEN_R: R45.1 U18.4 | length 62.2
  Top Layer w5.3: R45.1@1946.1,1300.24 U18.4@1946.1,1362.48
SOP_DRIVER_OEN: R45.2 R51.1 U61.1 U61.16 | length 576.9
  Top Layer w5.3: R45.2@1946.1,1252.99 R51.1@2001.1,1252.99 2060.82,1252.99 2304.25,1009.57 v1(2304.25,959.03)
  Bottom Layer w5.3: U61.1@2280.62,975.62 2280.62,959.42 2286.97,953.08 2298.3,953.08 v1(2304.25,959.03) U61.16@2304.25,981.53
SPI0_CLK/PR1_PRU1_GPIO16: J1/J3.7 U31.2 | length 6281.1
  Top Layer w5.3: v1(1942.64,898.21) 1939.2,898.21 1934.53,893.53 1933.95,893.53 1899.42,859.01 1899.42,728.42 1794.45,623.45 1396.72,623.45 1203.65,430.38 1203.65,289.68 1350.88,142.45 1350.88,78.8 1389.52,40.16 1994.33,40.16 J1/J3.7@2054.17,100 ; v1(3725.87,1742.47) 3726.72,1741.62 3750.27,1741.62 U31.2@3751.12,1740.77
  Bottom Layer w5.3: v1(1942.64,898.21) 1941.86,898.21 1925.84,914.22 1925.84,1041.58 1887.28,1080.15 1791.49,1080.15 1763.02,1108.62 1763.02,1274.89 1858.65,1370.52 1858.65,1670.31 1772.18,1756.77 1534.15,1756.77 1511.06,1779.86 1511.06,1942.02 1539.78,1970.73 1785.1,1970.73 1810.56,1945.27 1810.56,1877.38 1831.19,1856.74 1881.43,1856.74 1904.92,1880.23 1904.92,1919.44 1950.19,1964.71 2643.56,1964.71 2812.56,1795.71 2907.99,1795.71 2943.52,1760.18 2997.02,1760.18 3012.08,1775.24 3130.24,1775.24 3209.86,1854.86 3474.53,1854.86 3489.1,1854.86 3510.11,1833.85 3510.11,1783.05 3533.68,1759.48 3602.08,1759.48 3630.96,1730.6 3714.01,1730.6 v1(3725.87,1742.47)
SPI0_D0/PR1_PRU1_GPIO13: J2/J4.15 U31.4 | length 2039.9
  Top Layer w5.3: v1(3708.41,1694.68) 3715.13,1701.4 U31.4@3751.12,1701.4
  Bottom Layer w5.3: J2/J4.15@1954.17,1900 2008.15,1953.98 2639.73,1953.98 2808.8,1784.91 2900.91,1784.91 2938.58,1747.23 3003.29,1747.23 3020.99,1764.94 3134.5,1764.94 3214.13,1844.56 3484.83,1844.56 3499.81,1829.58 3499.81,1782.73 3499.81,1778.78 3500.11,1778.48 3529.42,1749.18 3533.37,1749.18 3597.39,1749.18 3628.74,1717.82 3685.26,1717.82 v1(3708.41,1694.68)
SPI0_D1/PR1_PRU1_GPIO10: J2/J4.14 U31.3 | length 1822.1
  Top Layer w5.3: v1(3669.23,1698.3) 3692.02,1721.09 U31.3@3751.12,1721.09
  Bottom Layer w5.3: J2/J4.14@2054.17,1900 2096.55,1857.62 2587.88,1857.62 2708.39,1737.11 2815.04,1737.11 2836.82,1758.89 2909.24,1758.89 2933.35,1734.78 3009.76,1734.78 3026.78,1751.79 3512.23,1751.79 3525.15,1738.88 3526.91,1738.88 3527.03,1738.75 3592.09,1738.75 3632.54,1698.3 v1(3669.23,1698.3)
TA_GPIO1: Q4.1 R37.2 R373.2 | length 857.4
  Top Layer w5.3: R37.2@1628.41,1637.95 v1(1663.62,1637.95)
  Bottom Layer w5.3: Q4.1@1188.73,2096.74 1187.57,2095.58 1187.57,1984.68 1201.92,1970.33 1361.75,1970.33 1413.14,1918.94 1413.14,1783 1533.94,1662.2 1621.87,1662.2 1628.41,1655.66 R373.2@1628.41,1637.95 v1(1663.62,1637.95)
TA_GPIO1_XDS: R388.2 U9.2 U63.74 | length 707.4
  Top Layer w5.3: U9.2@1118.64,1637.95 1175.72,1637.95 v1(1177.39,1636.27)
  Bottom Layer w5.3: U63.74@948.65,1276.73 1142.1,1276.73 1229.01,1363.64 1229.01,1587.72 1180.45,1636.27 v1(1177.39,1636.27) 1175.72,1637.95 R388.2@1142.27,1637.95
TA_GPIO2: R400.2 R401.2 TP57.1 | length 90.1
  Bottom Layer w5.3: R401.2@777.09,1825.69 R400.2@827.09,1825.69 855.1,1825.69 TP57.1@863.64,1834.23
TA_GPIO2_XDS: R397.2 U7.2 U63.73 | length 521.2
  Top Layer w5.3: v1(830.33,1685.11) 827.09,1681.86 U7.2@827.09,1632.31 827.09,1597.72 842.24,1582.56 842.24,1353.55 v1(892.5,1303.29)
  Bottom Layer w5.3: R397.2@830.33,1634.77 v1(830.33,1685.11) ; v1(892.5,1303.29) 903.32,1292.48 U63.73@948.65,1292.48
TA_GPIO3: J9.2 R36.2 R372.2 U18.1 | length 404.8
  Top Layer w5.3: R36.2@1628.41,1587.95 v1(1663.62,1587.95) 1713.62,1537.95 1774.37,1537.95 1837.83,1474.48 U18.1@1837.83,1437.28
  Bottom Layer w5.3: R372.2@1628.41,1587.95 v1(1663.62,1587.95) J9.2@1739.61,1587.95
TA_GPIO3_PD: J9.1 R374.2 | length 112.1
  Bottom Layer w5.3: R374.2@1628.41,1687.95 1629.49,1686.86 1738.53,1686.86 J9.1@1739.61,1687.95
TA_GPIO3_XDS: R387.2 U9.3 U63.72 | length 631.3
  Top Layer w5.3: U9.3@1118.64,1587.95 v1(1177.39,1587.95)
  Bottom Layer w5.3: U63.72@948.65,1308.23 982.28,1308.23 998.03,1292.48 1135.3,1292.48 1214.32,1371.5 1214.32,1552.4 1178.78,1587.95 v1(1177.39,1587.95) R387.2@1142.27,1587.95
TA_GPIO4: R35.2 R371.2 U16.1 | length 883.4
  Top Layer w5.3: R35.2@1628.41,1537.95 v1(1663.62,1537.95) ; U16.1@1864.25,1010.01 1881.95,1010.01 1888.79,1003.16 v1@1888.79,965.62
  Bottom Layer w5.3: R371.2@1628.41,1537.95 v1(1663.62,1537.95) 1710.67,1537.95 1736.54,1512.07 1736.54,1028.02 1796.01,968.54 1888.79,968.54 v1(1888.79,965.11)
TA_GPIO4_XDS: R386.2 U9.4 U63.71 | length 555.7
  Top Layer w5.3: U9.4@1118.64,1537.95 1176.8,1537.95 v1(1177.39,1538.54)
  Bottom Layer w5.3: U63.71@948.65,1323.98 988.02,1323.98 1007.71,1304.29 1127.2,1304.29 1200.54,1377.63 1200.54,1516.18 1178.19,1538.54 v1(1177.39,1538.54) 1176.8,1537.95 R386.2@1142.27,1537.95
TA_I2C_SCL: R403.1 R405.2 U16.12 | length 1749
  Top Layer w5.3: v1(1726.09,1010.01) U16.12@1754.01,1010.01
  Bottom Layer w5.3: R405.2@591.82,1823.49 R403.1@641.82,1823.49 641.82,1803.61 648.14,1797.28 1345.41,1797.28 1378.44,1764.26 1378.44,1424.37 1713.23,1089.58 1713.23,1022.86 v1(1726.09,1010.01)
TA_I2C_SDA: R407.2 R409.1 U16.13 | length 1978.4
  Top Layer w5.3: v1(1747.95,957.83) 1773.97,957.83 1779.6,963.47 U16.13@1779.6,984.42
  Bottom Layer w5.3: R407.2@541.82,1823.49 R409.1@491.82,1823.49 491.82,1799.25 506.7,1784.36 1338.87,1784.36 1366.11,1757.12 1366.11,1415.45 1701.46,1080.1 1701.46,1004.33 v1(1747.95,957.83)
TA_PORZ: Q6.1 R34.2 R370.2 R408.1 | length 2100.5
  Top Layer w5.3: R34.2@1628.41,1487.95 v1(1663.62,1487.95)
  Bottom Layer w5.3: Q6.1@383.74,2016.24 459.9,1940.09 514.37,1940.09 518.69,1944.41 R408.1@541.97,1944.41 821.23,1944.41 950.67,1814.97 1344.53,1814.97 1389.24,1770.27 1389.24,1432.1 1541.09,1280.24 1675.33,1280.24 1698.78,1303.7 1698.78,1452.79 v1(1663.62,1487.95) R370.2@1628.41,1487.95
TA_PORZn_XDS: R385.2 U9.5 U63.77 | length 534.5
  Top Layer w5.3: U9.5@1118.64,1487.95 v1(1178.78,1487.95)
  SIG 1 w4.75: v1(903.32,1230.74) 903.9,1230.16 937.24,1230.16 1178.78,1471.7 v1(1178.78,1487.95)
  Bottom Layer w5.3: v1(903.32,1230.74) 904.57,1229.49 U63.77@948.65,1229.49 ; R385.2@1142.27,1487.95 v1(1178.78,1487.95)
TA_POWERDOWNZ: R32.2 R368.2 U10.2 | length 1581.3
  Top Layer w5.3: U10.2@1123.03,276.85 1123.03,318.62 v1(1124.06,319.66) ; R32.2@1628.41,1387.95 v1(1663.62,1387.95)
  SIG 1 w4.75: v1(1124.06,319.66) 1123.48,320.23 1123.48,469.5 1174.3,520.31 1304.7,520.31 1409.52,625.14 1409.52,1302.82 1494.66,1387.95 v1(1663.62,1387.95)
  Bottom Layer w5.3: R368.2@1628.41,1387.95 v1(1663.62,1387.95)
TA_PWRDNz_XDS: R383.2 U9.7 U63.78 | length 593.2
  Top Layer w5.3: U9.7@1118.64,1387.95 v1(1178.78,1387.95)
  SIG 1 w4.75: v1(861.83,1229.53) 882.16,1209.19 1000.02,1209.19 v1(1178.78,1387.95)
  Bottom Layer w5.3: v1(861.83,1229.53) 882.13,1209.22 909.41,1209.22 913.93,1213.74 U63.78@948.65,1213.74 ; R383.2@1142.27,1387.95 v1(1178.78,1387.95)
TA_RESETZ: Q5.1 R33.2 R369.2 | length 1384.8
  Top Layer w5.3: R33.2@1628.41,1437.95 1652.28,1437.95 1660.19,1445.86 v1(1663.62,1445.86)
  Bottom Layer w5.3: Q5.1@1080.13,2007.56 1118.89,2007.56 1169.26,1957.19 1356.05,1957.19 1402.54,1910.7 1402.54,1449.57 1543.88,1308.23 1665.57,1308.23 1684.69,1327.34 1684.69,1438.99 1677.82,1445.86 1661.93,1445.86 1654.17,1438.1 1628.56,1438.1 R369.2@1628.41,1437.95
TA_RESETz_XDS: R384.2 TP8.1 U9.6 U63.76 | length 457.2
  Top Layer w5.3: TP8.1@948.65,1245.24 v1(994.37,1245.24) ; U9.6@1118.64,1437.95 v1(1178.78,1437.95)
  SIG 1 w4.75: v1(994.37,1245.24) 1178.78,1429.64 v1(1178.78,1437.95)
  Bottom Layer w5.3: U63.76@948.65,1245.24 v1(994.37,1245.24) ; R384.2@1142.27,1437.95 v1(1178.78,1437.95)
TCA_ADDR: R43.2 U16.16 | length 77.5
  Top Layer w5.3: U16.16@1838.66,984.42 1838.66,942.73 1851.28,930.1 R43.2@1869.25,930.1
TCA_INTN: R39.2 U16.11 | length 63.2
  Top Layer w5.3: R39.2@1690.78,1029.69 U16.11@1754.01,1029.69
TM4C129_TCK: TP6.1 U63.100 | length 106
  Top Layer w5.3: TP6.1@853.9,770 v1(853.9,798.54)
  Bottom Layer w5.3: U63.100@842.35,871.22 842.35,837.26 847.01,832.59 847.01,805.43 v1(853.9,798.54)
TM4C129_TDI: TP10.1 U63.98 | length 161.9
  Top Layer w5.3: TP10.1@955.9,769 v1(955.9,797.54)
  Bottom Layer w5.3: U63.98@873.85,871.22 873.85,835.75 891.53,818.07 935.37,818.07 v1(955.9,797.54)
TM4C129_TDO: TP11.1 U63.97 | length 192.8
  Top Layer w5.3: v1(1000,797.13) 1000,796.57 1008.9,787.67 TP11.1@1008.9,769
  Bottom Layer w5.3: U63.97@889.59,871.22 889.59,837.33 898.25,828.67 968.46,828.67 v1(1000,797.13)
TM4C129_TMS: TP7.1 U63.99 | length 131.8
  Top Layer w5.3: TP7.1@903.9,770 v1(903.9,798.54)
  Bottom Layer w5.3: U63.99@858.1,871.22 858.1,824.48 884.04,798.54 v1(903.9,798.54)
TPS_CT: C38.1 U14.6 | length 64
  Top Layer w10: U14.6@1654.12,383.84 1694.99,383.84 C38.1@1711.37,367.46
TPS_VSYS_5V0_ON: R31.1 U10.4 U14.3 | length 585.6
  Top Layer w8: U10.4@1160.43,385.12 v1(1160.43,425.78)
  Top Layer w10: v1(1521.89,305.62) R31.1@1556.6,305.62 1556.6,330.93 1553.81,333.71 1553.81,373.8 1563.77,383.76 1579.24,383.76 U14.3@1579.32,383.84
  SIG 1 w8: v1(1160.43,425.78) 1188.44,397.77 1429.74,397.77 v1(1521.89,305.62)
TUSB_ADDR: TP4.1 U6.5 | length 125.3
  Top Layer w5.3: U6.5@693.44,191.16 693.44,165.94 708.66,150.72 708.66,129.9 TP4.1@749.46,89.1
TUSB_EN_N: R15.2 U6.11 | length 96.6
  Top Layer w5.3: U6.11@677.69,250.21 677.61,250.29 677.61,263.66 673.56,267.7 673.56,306.2 682.76,315.39 R15.2@708.66,315.39
TUSB_ID: TP5.1 U6.9 | length 171.3
  Top Layer w5.3: U6.9@709.19,250.21 709.27,250.29 709.27,263.32 806.92,360.97 TP5.1@806.92,381.05
TUSB_OUT: R25.1 U8.4 U10.1 | length 129
  Top Layer w5.3: U8.4@960.35,269.73 1015.94,269.73 R25.1@1016.9,268.77 1055.65,268.77 1063.73,276.85 U10.1@1085.63,276.85
TUSB_OUT1: R17.2 R20.2 U8.1 | length 152.9
  Top Layer w5.3: R17.2@797.87,199.9 816.06,199.9 822.44,193.53 R20.2@855.31,193.53 881.44,193.53 891.34,183.63 912.84,183.63 920.98,191.77 U8.1@920.98,211.46
TUSB_OUT1_R: R17.1 U6.7 | length 52.7
  Top Layer w5.3: U6.7@711.15,212.81 728.98,212.81 741.85,199.95 R17.1@758.5,199.9 R17.1@758.5,199.9
TUSB_OUT2: R18.2 R21.2 U8.2 | length 181.4
  Top Layer w5.3: R18.2@797.87,240.01 819.53,240.01 836.18,256.66 R21.2@855.31,256.66 885.37,256.66 898.17,243.86 930.37,243.86 940.66,233.56 U8.2@940.66,211.46
TUSB_OUT2_R: R18.1 U6.8 | length 52.1
  Top Layer w5.3: U6.8@711.15,228.56 729.74,228.56 741.2,240.01 R18.1@758.5,240.01
TUSB_OUT3: R16.1 U6.6 | length 81.7
  Top Layer w5.3: U6.6@709.19,191.16 709.19,170.6 719.19,160.6 741.85,160.6 749.25,153.19 R16.1@749.25,139.29
TUSB_PORT: R13.2 U6.3 | length 73.9
  Top Layer w5.3: R13.2@627.02,131.7 627.02,135.63 661.94,170.55 U6.3@661.94,191.16
TUSB_VBUS_DET: R14.1 U6.4 | length 60.2
  Top Layer w5.3: U6.4@677.69,191.16 677.69,134.14 R14.1@679.97,131.86
UART5_RXD/PR1_PRU1_GPIO8: J5/J7.43 U31.12 | length 6109.8
  Top Layer w5.3: v1(3715.1,1543.92) U31.12@3751.12,1543.92
  SIG 1 w4.75: v1(2566.86,1199.12) 2566.86,1119.53 2612.85,1073.55 2612.85,942.46 2583.15,912.76 2499.41,912.76 2478.52,891.87 2478.52,842.17 2432.32,795.97 2134.29,795.97 1682,343.68 1682,267.79 1708.96,240.83 1708.96,73.26 1725.2,57.02 1880.78,57.02 1904.17,80.41 1904.17,121.44 1928.83,146.1 2404.36,146.1 2493.48,235.21 2951.94,235.21 3009.25,177.9 3098.11,177.9 3251.13,24.88 3485.89,24.88 3546.01,85 3731.92,85 3740.34,76.58 3906.04,76.58 3924.22,58.4 4112.57,58.4 J5/J7.43@4154.17,100
  Bottom Layer w5.3: v1@2567.17,1199.12 2567.59,1199.54 2567.59,1571.77 2630.57,1634.74 3097.74,1634.74 3129,1666 3357.9,1666 3461.49,1562.41 3497.09,1562.41 3507.37,1572.69 3627.43,1572.69 3636.88,1563.23 3637.29,1563.23 3637.59,1562.93 3696.09,1562.93 v1(3715.1,1543.92)
UART5_TXD/PR1_PRU1_GPIO7: J5/J7.44 U31.13 | length 6174.4
  Top Layer w5.3: v1(3681.89,1513.05) 3681.89,1513.94 3692.19,1524.24 U31.13@3751.12,1524.24
  SIG 1 w4.75: v1(2568.43,1009.61) 2485.61,1009.61 2431.29,955.28 2431.29,833.18 2418.01,819.9 2140.12,819.9 1672,351.78 1672,264 1699.21,236.79 1699.21,68.02 1718.87,48.36 1720.07,48.36 1721.16,47.27 2366.72,47.27 2399.67,80.22 2399.67,127.62 2479.57,207.52 2688.6,207.52 2728.87,167.25 3094.98,167.25 3247.09,15.13 3489.93,15.13 3546,71.2 3729.57,71.2 3734.49,66.28 3899.11,66.28 3917.03,48.36 4202.54,48.36 J5/J7.44@4254.17,100
  Bottom Layer w5.3: v1(2568.43,1009.61) 2599.16,1040.34 2599.16,1215.86 2624.26,1240.96 2624.26,1292.23 2599.16,1317.33 2599.16,1559.57 2653.74,1614.14 3118.47,1614.14 3141.35,1637.03 3257.11,1637.03 3409.32,1484.81 3559.97,1484.81 3588.21,1513.05 v1(3681.89,1513.05)
USB0_DRVVBUS_SW: R66.1 SW6.2 U22.4 | length 572.1
  Top Layer w5.3: U22.4@2395.2,442.34 2395.2,470.53 2415.21,490.54 R66.1@2415.21,517.92 2441.11,517.92 2450.95,527.75 v1(2450.95,541.93) ; v1(2561.96,666.9) 2621.73,666.9 2632.62,656.01 2698.2,656.01 2730.02,687.83 SW6.2@2730.02,731.93
  Bottom Layer w5.3: v1(2450.95,541.93) 2452.17,543.16 2452.17,576.74 2487.07,611.64 2487.07,649.07 2497.98,659.98 2552.5,659.98 2559.43,666.9 v1(2561.96,666.9)
USB0_VBUS_OC: R360.2 U22.3 U29.14 | length 3300.2
  Top Layer w5.3: v1(2002.86,1633.95) 2002.86,1403.31 2091.36,1314.81 2152.24,1314.81 2234.43,1232.62 2285.79,1232.62 2352,1166.41 2352,922.35 2337.39,907.75 2334.11,907.75 2294.87,868.5 2294.87,656.05 2346.87,604.05 2452.09,604.05 2452.21,603.94 2468.38,603.94 2468.5,604.05 2509.78,604.05 2518.8,595.03 v1(2518.8,494.68) 2503.47,479.34 U22.3@2503.47,442.34 ; v1(3513,1656) 3514.98,1654.02 3514.98,1618.95 U29.14@3514.18,1618.16
  Bottom Layer w5.3: v1(2002.86,1633.95) 2025.12,1656.21 2588.34,1656.21 2608.07,1675.94 3016.86,1675.94 3051.51,1710.59 3488.75,1710.59 3500.78,1698.56 3500.78,1668.22 v1(3513,1656) ; R360.2@2506.66,442.93 2506.66,482.53 v1(2518.8,494.68)
USB0_VBUS_OC_L: U29.7 U34.J1 | length 849.8
  Top Layer w5.3: U29.7@3514.18,1488.24 3514.18,1473.47 3641.76,1345.89 3641.76,1211.9 3706.66,1147 3706.66,1130.71 v1(3724.76,1112.61) ; v1(3901.08,1089.99) 3903.97,1092.88 3908.16,1097.07 3967.04,1097.07 3971.23,1092.88 4079.62,1092.88 U34.J1@4094.49,1092.88
  Bottom Layer w5.3: v1(3724.76,1112.61) 3727.19,1115.04 3732.78,1115.04 3734.22,1116.48 3822.21,1116.48 3848.7,1089.99 v1(3901.08,1089.99)
USB2.0_MUX_SEL0: R65.2 R354.1 R355.2 U59.11 | length 849.7
  Top Layer w5.3: v1(2325.69,707.38) 2336.11,717.8 R65.2@2357.14,717.8
  SIG 1 w5.3: v1(2325.69,707.38) 2325.69,659.89 2350.04,635.54 2437.45,635.54 2455.33,653.42 2455.33,747.08 2478.96,770.71 2558.92,770.71 2603.05,726.58 2703.09,726.58 2731.47,698.2 2731.47,660.57 v1(2730.44,659.54)
  Bottom Layer w5.3: U59.11@2675.31,584.08 2675.31,583.19 2676.6,581.91 2684.09,581.91 2707.08,558.92 2724.46,558.92 R354.1@2727.67,555.71 2727.67,596.05 R355.2@2731.61,599.99 2731.61,658.38 v1(2730.44,659.54)
USBMICROAB_1_ID: J10.4 R356.2 SW5.1 U24.4 U24.7 | length 504.2
  Top Layer w5.3: J10.4@2682.86,46.17 2682.86,102.4 2693.69,113.22 U24.4@2693.69,142.95 2693.69,162.95 U24.7@2693.69,175.83 2693.69,195.83 2693.69,233.37 2748.85,288.53 2748.85,415.73 v1(2726.22,438.36) SW5.1@2726.22,474.92
  Bottom Layer w5.3: v1(2726.22,438.36) 2731.54,443.67 R356.2@2731.54,474.92
USBMICROAB_C_DM: L2.3 R72.1 R78.1 U59.5 | length 275.3
  Top Layer w4.2: v1(2611.47,475.4) 2632.14,475.4 2639.81,467.73 2639.81,446.68 2637.35,444.22 2630.2,444.22 R78.1@2620.49,434.51 2620.49,385.65 R72.1@2619.95,385.11 ; R72.1@2616.01,385.11 R72.1@2619.95,385.11 ; L2.3@2628.15,305.4 2628.15,327.18 2638.72,337.76 2638.72,366.33 R72.1@2619.95,385.11
  Bottom Layer w4.2: v1@2611.47,476.4 2612.32,477.24 U59.5@2612.32,528.96
USBMICROAB_C_DP: L2.2 R78.2 R80.1 U59.1 | length 274.4
  Top Layer w4.2: L2.2@2659.65,305.4 2659.65,327.58 2647.92,339.31 2647.92,365.36 2667.67,385.11 R80.1@2671.61,385.11 2667.73,388.98 R78.2@2667.73,434.51 2658.02,444.22 2651.47,444.22 2649.01,446.68 2649.01,468.33 2656.08,475.4 v1(2674.47,475.4)
  Bottom Layer w4.2: v1@2674.47,476.4 2675.31,477.24 U59.1@2675.31,528.96
USBMICROAB_DM: J10.2 L2.4 U24.1 U24.10 | length 204.9
  Top Layer w4.2: L2.4@2628.15,238.47 2628.15,215.35 2639.51,203.99 2639.51,187.31 2637.05,184.85 2636.47,184.85 2634.63,183.01 U24.1@2634.63,142.95 2634.63,122.76 2639.88,117.52 2639.88,83.6 2631.68,75.41 J10.2@2631.68,46.17
USBMICROAB_DP: J10.3 L2.1 U24.2 U24.9 | length 205.1
  Top Layer w4.2: J10.3@2657.27,46.17 2657.27,76.44 2649.08,84.63 2649.08,87.42 2649.08,113.71 2649.08,117.52 2654.32,122.76 U24.2@2654.32,142.95 2654.32,183.01 2652.48,184.85 2651.91,184.85 2648.71,188.05 2648.71,204.03 2659.65,214.96 L2.1@2659.65,238.47
USBTYPEC_C_DM: L6.2 U59.4 | length 2337.8
  Bottom Layer w4.2: L6.2@516.53,543.12 516.65,543 538.09,543 541.51,539.58 541.51,527.24 547.93,520.82 631.74,520.82 668.69,483.87 2078.53,483.87 2139.63,422.77 2294.43,422.77 2338.47,378.73 2609.72,378.73 2638.61,407.62 2638.61,479.39 2624.74,493.25 2624.74,508.02 2628.07,511.34 U59.4@2628.07,528.96
USBTYPEC_C_DP: L6.3 U59.2 | length 2337
  Bottom Layer w4.2: L6.3@516.53,511.62 539.66,511.62 627.93,511.62 662.19,477.36 664.88,474.67 2074.72,474.67 2135.82,413.57 2290.62,413.57 2319.29,384.9 2331.97,372.23 2334.66,369.53 2613.53,369.53 2647.81,403.81 2647.81,461.21 2647.81,479.19 2662.7,494.09 2662.7,508.03 2659.56,511.17 U59.2@2659.56,528.96
USBTYPEC_CC1: J25.A5 R411.2 U6.1 U65.1 U65.10 | length 643.6
  Top Layer w5.3: J25.A5@176.63,390.63 212.07,390.63 v1(212.56,390.13) ; v1(622.36,237.37) 630.74,229 659.53,229 U6.1@659.97,228.56
  Bottom Layer w5.3: v1(212.56,390.13) 215.74,390.13 283.5,457.9 U65.1@306.02,457.9 U65.10@338.89,457.9 356.76,457.9 375.15,439.51 R411.2@399.15,439.51 399.15,421.83 404.77,416.22 488.97,416.22 511.64,393.55 511.64,348.09 v1(622.36,237.37)
USBTYPEC_CC2: J25.B5 U6.2 U65.2 U65.9 | length 1156
  Top Layer w5.3: v1(69.85,292.13) 70.13,292.41 70.13,305.22 85.31,320.39 108.37,320.39 J25.B5@109.7,321.73 ; v1(622.03,205.39) 629.45,212.81 U6.2@659.97,212.81
  Bottom Layer w5.3: v1(69.85,292.13) 69.85,271.44 97.5,243.79 173.39,243.79 214.15,284.55 214.15,359.55 192.61,381.09 192.61,401.79 268.41,477.58 U65.2@306.02,477.58 U65.9@338.89,477.58 369.87,477.58 382.47,464.99 463.36,464.99 474.32,454.03 590.72,454.03 664.35,380.4 664.35,247.71 v1(622.03,205.39)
